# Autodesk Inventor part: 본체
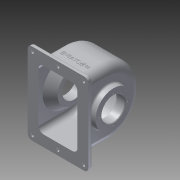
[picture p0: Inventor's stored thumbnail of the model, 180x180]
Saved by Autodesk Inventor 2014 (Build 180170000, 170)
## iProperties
Created: 2015-09
Part Number: 본체
Material: 알루미늄 6061
Document SubType Name: Modeling
Designer: Owner
Density: 2.71 g/cm^3
Appearance: 알루미늄 - 평지
Author: Owner
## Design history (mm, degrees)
sketch "스케치2"
  geometry: L1 (0, 57)-(-47, 57); L2 (-47, 57)-(-47, -57); L3 (-47, -57)-(0, -57); A1 r 57 centre (0, 0) between (0, -57) and (0, 57); 1 further point
  constraints: 6 end point, 2 point on circle, 2 tangent, 1 centre point, 1 coincident, 1 horizontal, 1 parallel, 1 perpendicular
  dimensions: "d4" = 47 distance of L1.start L1.end; "d5" = 114 distance of L1.end L2.end
extrude "돌출1" new body sketch "스케치2" distance "d6" = 77; taper "d7" = 0 deg
feature "쉘1" dims "d8" = 5
sketch "스케치3"
  geometry: C1 r 31 at (0, 0); A1 r 57 centre (0, 0) between (57, 0) and (-57, 0) reference
  constraints: 1 centre point, 1 coincident
  dimensions: "d10" = 62 diameter of C1
extrude "돌출2" join sketch "스케치3" distance "d11" = 10; taper "d12" = 0 deg
sketch "스케치4"
  geometry: C1 r 31 at (0, 0) reference
hole "구멍1" sketch "스케치4" at (0, 0) diameter "d13" = 40; stored, may be unused: countersink angle "d17" = 90 deg, drill point angle "d19" = 118 deg; dims "d14" = 6, "d15" = 4, "d16" = 2, "d18" = 20
chamfer "모따기1" distance "d20" = 1; stored, may be unused: second distance "d21" = 2, angle "d22" = 45 deg
sketch "스케치6"
  geometry: L1 (77, 114)-(77, 0) reference; L2 (0, 57)-(77, 57); L3 (-13.5, -13)-(90.5, -13); L4 (90.5, -13)-(90.5, 127); L5 (90.5, 127)-(-13.5, 127); L6 (-13.5, 127)-(-13.5, -13); L7 (38.5, -13)-(38.5, 127); L8 (0, 114)-(77, 114); L9 (77, 114)-(77, 0); L10 (77, 0)-(0, 0); L11 (0, 0)-(0, 114); 2 further points
  constraints: 20 end point, 5 midpoint, 4 parallel, 2 coincident, 2 horizontal, 2 perpendicular
  dimensions: "d26" = 104 distance of L5.end L4.end; "d27" = 140 distance of L4.end L3.end
extrude "돌출4" join sketch "스케치6" distance "d28" = 7; taper "d29" = 0 deg
node "작업 평면1"
sketch "스케치8"
  geometry: L1 (13.5, 70)-(13.5, -70) reference; L2 (13.5, -70)-(-90.5, -70) reference; L3 (-90.5, -70)-(-90.5, 70) reference; L4 (-90.5, 70)-(13.5, 70) reference; L5 (-72, -52)-(-5, -52) reference; L6 (-5, -52)-(-5, 52) reference; L7 (-5, 52)-(-72, 52) reference; L8 (-72, 52)-(-72, -52) reference; L9 (0, -57)-(-77, -57) reference; L10 (-77, -57)-(-77, 57) reference; L11 (-77, 57)-(0, 57) reference; L12 (0, 57)-(0, -57) reference; 1 further point
extrude "돌출5" cut sketch "스케치8" distance "d31" = 7; taper "d32" = 0 deg
sketch "스케치10"
  geometry: L1 (-13.5, 13)-(-13.5, -127) reference; L2 (90.5, -127)-(90.5, 13) reference; L3 (-5.5, -119)-(82.5, -119); L4 (82.5, -119)-(82.5, 5); L5 (82.5, 5)-(-5.5, 5); L6 (-5.5, 5)-(-5.5, -119); L7 (-13.5, -57)-(90.5, -57); L8 (38.5, 5)-(38.5, -119); C1 r 2.5 at (-5.5, 5); C2 r 2.5 at (38.5, 5); C3 r 2.5 at (82.5, 5); C4 r 2.5 at (82.5, -119); C5 r 2.5 at (38.5, -119); C6 r 2.5 at (-5.5, -119); 3 further points
  constraints: 12 end point, 8 coincident, 6 centre point, 6 midpoint, 2 parallel, 1 horizontal, 1 perpendicular
  dimensions: "d43" = 88 distance of L5.end L4.end; "d44" = 124 distance of L4.end L3.end; "d45" = 5 diameter of C1; "d46" = 5 diameter of C2; "d47" = 5 diameter of C3; "d48" = 5 diameter of C4; "d49" = 5 diameter of C5; "d51" = 5 diameter of C6
extrude "돌출7" cut sketch "스케치10" distance "d52" = 7; taper "d53" = 0 deg
fillet "모깎기1" dims "d54" = 14
node "작업 평면2"
sketch "스케치12"
  geometry: L1 (86, -20)-(87, -21) reference; L2 (87, -21)-(87, -31) reference; L3 (87, -31)-(77, -31) reference; L4 (77, -31)-(77, -40) reference; L5 (77, -40)-(90.5, -40) reference; L6 (90.5, -40)-(90.5, -47) reference; L7 (90.5, -47)-(72, -47) reference; L8 (72, -47)-(72, -20) reference; L9 (72, -20)-(86, -20) reference; L10 (87, 21)-(86, 20) reference; L11 (86, 20)-(72, 20) reference; L12 (72, 20)-(72, 52) reference; L13 (72, 52)-(5, 52) reference; L14 (5, 52)-(5, -47) reference; L15 (5, -47)-(-13.5, -47) reference; L16 (-13.5, -47)-(-13.5, -40) reference; L17 (-13.5, -40)-(0, -40) reference; L18 (0, -40)-(0, 43) reference; L19 (14, 57)-(63, 57) reference; L20 (77, 43)-(77, 31) reference; L21 (77, 31)-(87, 31) reference; L22 (87, 31)-(87, 21) reference; L23 (0, 0)-(19, 0); L24 (19, 0)-(19, 28); L25 (0, 37.416)-(4.21, 33.883); L26 (3.889, 33)-(3, 33); L27 (3, 33)-(3, 0); L28 (0, 37.416)-(0, 0); L29 (0.496, 37)-(3.71, 40.83); L30 (19, 28)-(3.71, 40.83); L31 (0.03, 43.918)-(0, 43.943); A1 r 14 centre (14, 43) between (14, 57) and (0, 43) reference; A2 r 14 centre (63, 43) between (77, 43) and (63, 57) reference; A3 r 0.5 centre (3.889, 33.5) between (3.889, 33) and (4.21, 33.883)
  constraints: 18 end point, 5 perpendicular, 4 point on line, 3 point on circle, 2 parallel, 2 tangent, 1 centre point, 1 collinear
  dimensions: "d60" = 56 diameter of L24.end L23; "d64" = 66 diameter of L26.end L23; "d68" = 16 distance between parallel lines of L24 L27; "d69" = 3 distance between parallel lines of L27 L18; "d71" = 0.5 radius of A3; "d88" = 130 deg angle of L6 L30; "d89" = 5 distance between parallel lines of L30 L25; "d90" = 0 distance between parallel lines of L30 L31; "d91" = 118.44202 distance from line of L5.end L29
  node "절단 모서리 투영3"
revolve "회전1" stored, may be unused: angle "d72" = 90 deg
sketch "스케치13"
  geometry: 1 further point
revolve "회전2" stored, may be unused: angle "d73" = 90 deg
sketch "스케치14"
  geometry: C1 r 33 at (0, 0) reference; C2 r 20 at (0, 0)
  constraints: 1 centre point, 1 coincident
  dimensions: "d74" = 40 diameter of C2
extrude "돌출9" cut sketch "스케치14" distance "d75" = 20; taper "d76" = 0 deg
chamfer "모따기2" distance "d77" = 1; stored, may be unused: second distance "d78" = 2, angle "d79" = 50 deg
sketch "스케치15"
  geometry: C1 r 21 at (0, 0) reference; A1 r 28 centre (0, 0) between (0, 28) and (28, 0); 2 further points
  constraints: 4 point on circle, 1 centre point, 1 coincident
  dimensions: "d80" = 56 diameter of A1
hole "구멍2" sketch "스케치15" at (0, 28), (28, 0), (0, -28), (-28, 0) diameter "d81" = 2.459; stored, may be unused: countersink angle "d85" = 90 deg, drill point angle "d87" = 118 deg; dims "d82" = 7, "d83" = 4, "d84" = 2, "d86" = 9
fillet "모깎기3" dims "d93" = 3
sketch "스케치16"
  geometry: C1 r 21 at (0, 0) reference; A1 r 24 centre (0, 0) between (0, 24) and (24, 0); 2 further points
  constraints: 4 point on circle, 1 centre point, 1 coincident
  dimensions: "d94" = 48 diameter of A1
hole "구멍3" sketch "스케치16" at (0, 24), (24, 0), (0, -24), (-24, 0) diameter "d95" = 2.459; stored, may be unused: countersink angle "d99" = 90 deg, drill point angle "d101" = 118 deg; dims "d96" = 6, "d97" = 4, "d98" = 2, "d100" = 8
node "작업 평면5"
sketch "스케치19"
  geometry: L1 (19, -28)-(5, -39.747) reference; L2 (5, -39.747)-(5, -47) reference; L3 (5, -47)-(-13.5, -47) reference; L4 (-13.5, -47)-(-13.5, -40) reference; L5 (-13.5, -40)-(0, -40) reference; L6 (0, -40)-(0, -37.416) reference; L7 (0, -37.416)-(4.21, -33.883) reference; L8 (3.889, -33)-(3, -33) reference; L9 (3, -33)-(3, -29.23) reference; L10 (3, -29.23)-(12, -29.23) reference; L11 (12, -29.23)-(12.739, -28) reference; L12 (12.739, -28)-(12, -26.771) reference; L13 (12, -26.771)-(3, -26.771) reference; L14 (3, -26.771)-(3, -21) reference; L15 (3, -21)-(4, -20) reference; L16 (4, -20)-(19, -20) reference; L17 (19, -20)-(19, -28) reference; L18 (86, -20)-(87, -21) reference; L19 (87, -21)-(87, -22.771) reference; L20 (87, -22.771)-(79, -22.771) reference; L21 (79, -22.771)-(78.261, -24) reference; L22 (78.261, -24)-(79, -25.23) reference; L23 (79, -25.23)-(87, -25.23) reference; L24 (87, -25.23)-(87, -31) reference; L25 (87, -31)-(80, -31) reference; L26 (77, -34)-(77, -40) reference; L27 (77, -40)-(90.5, -40) reference; L28 (90.5, -40)-(90.5, -47) reference; L29 (90.5, -47)-(72, -47) reference; L30 (72, -47)-(72, -20) reference; L31 (72, -20)-(86, -20) reference; L32 (87, 21)-(86, 20) reference; L33 (86, 20)-(72, 20) reference; L34 (72, 20)-(72, 52) reference; L35 (5, 52)-(5, 39.747) reference; L36 (5, 39.747)-(19, 28) reference; L37 (19, 28)-(19, 20) reference; L38 (19, 20)-(4, 20) reference; L39 (4, 20)-(3, 21) reference; L40 (3, 21)-(3, 26.771) reference; L41 (3, 26.771)-(12, 26.771) reference; L42 (12, 26.771)-(12.739, 28) reference; L43 (12.739, 28)-(12, 29.23) reference; L44 (12, 29.23)-(3, 29.23) reference; L45 (3, 29.23)-(3, 33) reference; L46 (3, 33)-(3.889, 33) reference; L47 (4.21, 33.883)-(0, 37.416) reference; L48 (0, 37.416)-(0, 43) reference; L49 (14, 57)-(63, 57) reference; L50 (77, 43)-(77, 34) reference; L51 (80, 31)-(87, 31) reference; L52 (87, 31)-(87, 25.23) reference; L53 (87, 25.23)-(79, 25.23) reference; L54 (79, 25.23)-(78.261, 24) reference; L55 (78.261, 24)-(79, 22.771) reference; L56 (79, 22.771)-(87, 22.771) reference; L57 (87, 22.771)-(87, 21) reference; L58 (14, 43)-(63, 43); L59 (38.5, 43)-(38.5, 57); L60 (38.5, 57)-(38.5, 63); L61 (38.5, 63)-(44.5, 63); L62 (44.5, 63)-(46.122, 53.801); L63 (46.122, 53.801)-(38.5, 53.801); L64 (44.5, 63)-(44.5, 53.801)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; A1 r 0.5 centre (3.889, -33.5) between (4.21, -33.883) and (3.889, -33) reference; A2 r 3 centre (80, -34) between (80, -31) and (77, -34) reference; A3 r 0.5 centre (3.889, 33.5) between (3.889, 33) and (4.21, 33.883) reference; A4 r 14 centre (14, 43) between (14, 57) and (0, 43) reference; A5 r 14 centre (63, 43) between (77, 43) and (63, 57) reference; A6 r 3 centre (80, 34) between (77, 34) and (80, 31) reference; 1 further point
  constraints: 14 end point, 3 perpendicular, 2 midpoint, 2 point on line, 1 collinear, 1 parallel
  dimensions: "d106" = 6 distance of L59.end L60.end; "d107" = 6 distance of L60.end L61.end; "d108" = 10 deg angle of L64 L62
revolve "회전3" sketch "스케치19" stored, may be unused: angle "d109" = 90 deg
fillet "모깎기5" dims "d110" = 3
fillet "모깎기6" dims "d118" = 3
fillet "모깎기7" dims "d119" = 7
sketch "스케치21"
  geometry: L1 (-14, 0)-(-14, 43) reference; L2 (69.5, -47)-(-20.5, -47) reference; 1 further point
  constraints: 1 other
  dimensions: "d121" = 38.5 distance from line of L1 point (24.5, -17); "d122" = 30 distance from line of L2 point (24.5, -17)
feature "엠보싱1" sketch "스케치21" dims "d123" = 0.5, "d124" = 0
fillet "모깎기9" dims "d125" = 1
fillet "모깎기10" dims "d126" = 3
node "작업 평면6"
sketch "스케치22"
  geometry: 1 further point
sketch "스케치23"
  geometry: L1 (0, 0)-(0, 47) reference; L2 (-104, 47)-(-104, 0) reference; L3 (0, 0)-(-104, 0) reference; L4 (-103, 47)-(-103, 0); L5 (-1, 47)-(-1, 0); L6 (-103, 0)-(-1, 0); A1 r 52 centre (-52, 47) between (0, 47) and (-104, 47) reference; A2 r 51 centre (-52, 47) between (-1, 47) and (-103, 47)
  constraints: 6 end point, 2 perpendicular, 2 point on circle, 2 point on line, 2 tangent, 1 centre point, 1 coincident, 1 collinear
  dimensions: "d129" = 51 radius of A2
extrude "돌출10" join sketch "스케치23" stored distance "d130" = 10; taper "d131" = 0 deg
fillet "모깎기11" dims "d132" = 9
sketch "스케치24"
  geometry: C1 r 6 at (0, 0) reference; 1 further point
hole "구멍5" sketch "스케치24" at (0, 0) diameter "d133" = 4.459; stored, may be unused: countersink angle "d137" = 90 deg, drill point angle "d139" = 118 deg; dims "d134" = 20, "d135" = 4, "d136" = 2, "d138" = 20
node "솔리드1"
node "절단 모서리 투영2"
node "절단 모서리 투영5"
other parameters: "d3" = 57, "d58" = 0, "d61" = 50 deg, "d70" = 5, "d104" = 0, "d127" = 0, "d128" = 51
